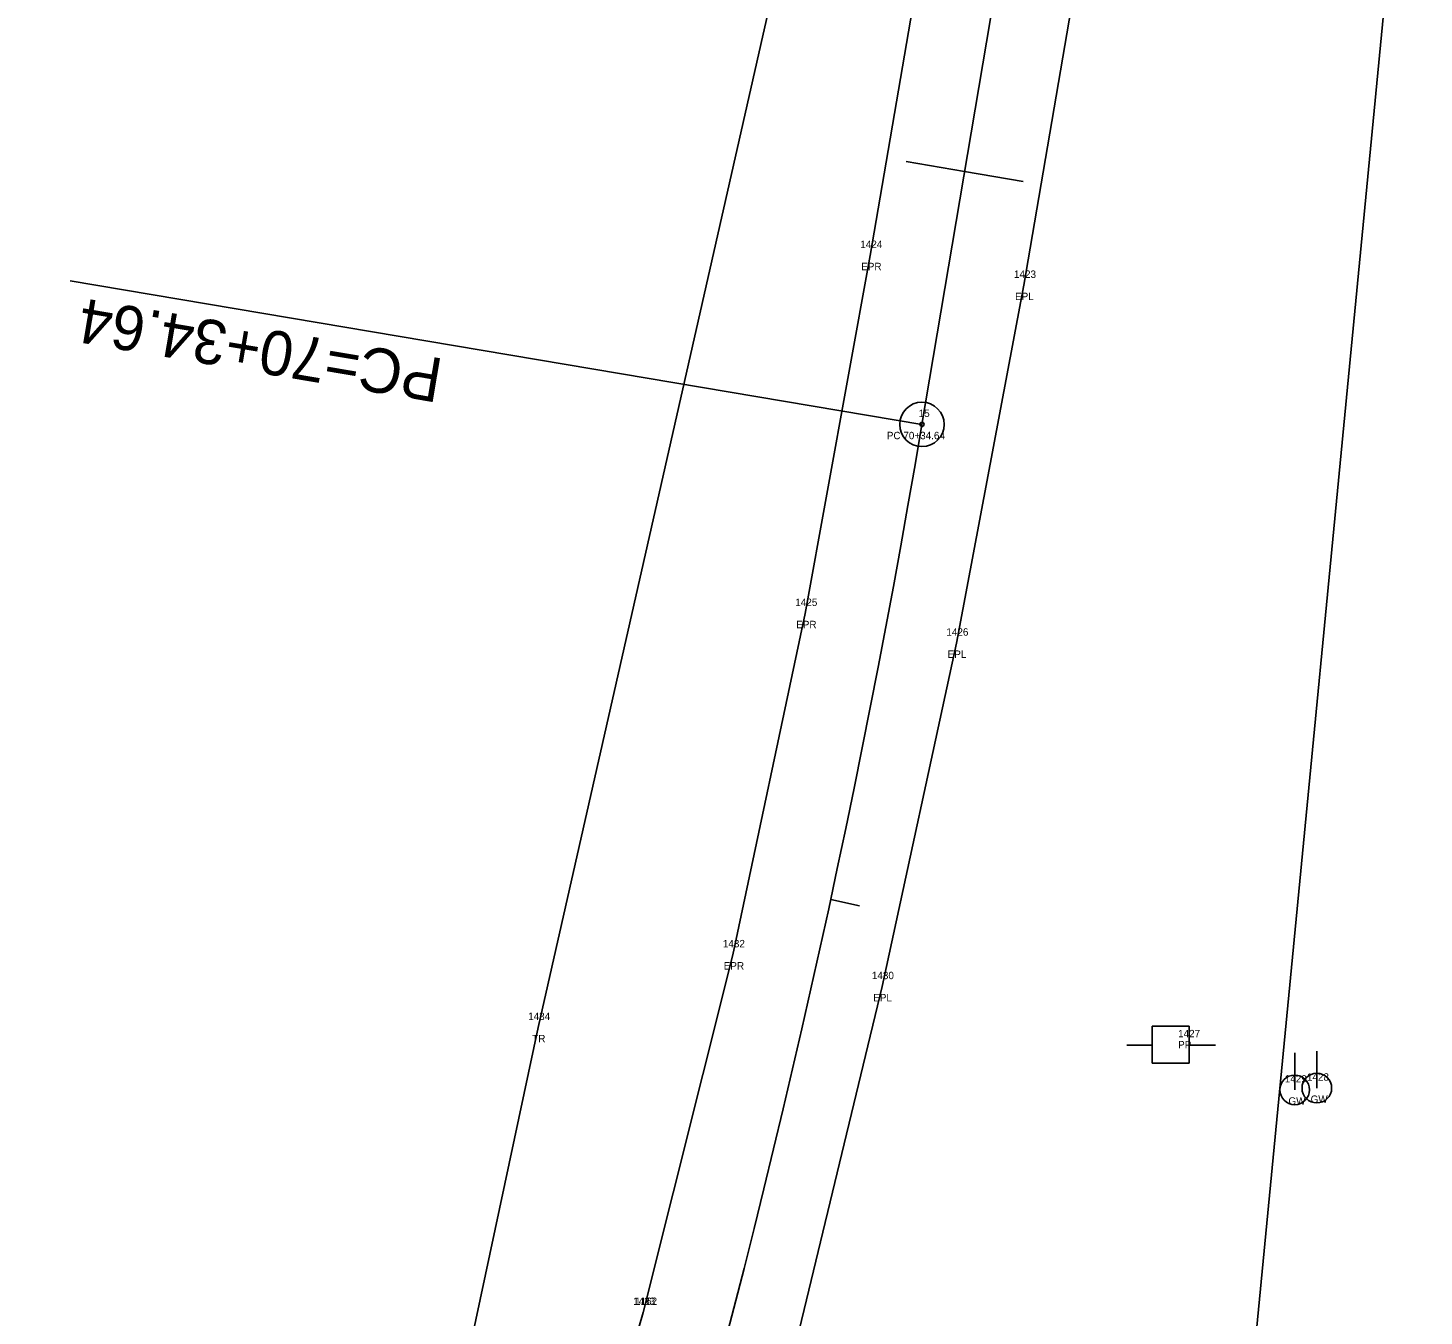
# Model space of a CAD drawing. Extents: x 2432632 to 2433497, y 684847 to 688233.
# Drawn here: x 2432974.5 to 2433163, y 685693.7 to 685867.7 of the extents above; entities that cross this region are included whole.
import ezdxf

# ---------------------------------------------------------------- set-up
doc = ezdxf.new("R2010")
doc.units = 0
for name, color, linetype in [('RD_EX_Road', 7, 'Continuous'), ('RD_EX_Road_txCode', 7, 'Continuous'), ('RD_EX_UT', 7, 'Continuous'), ('RD_EX_UT_txCode', 7, 'Continuous'), ('RD_EX_VEG', 7, 'Continuous'), ('RD_EX_VEG_txCode', 7, 'Continuous'), ('RD_HC_Cl', 7, 'Continuous'), ('RD_HC_Data', 7, 'Continuous'), ('RD_HC_Data_Tic', 7, 'Continuous'), ('RD_HC_txCode', 7, 'Continuous'), ('RD_SMD_Locator', 7, 'Continuous')]:
    doc.layers.add(name, color=color, linetype=linetype)

msp = doc.modelspace()

# ---------------------------------------------------------------- linework, layer by layer
at = {"layer": 'RD_EX_Road'}
for points in [[(2433117.43, 686021.83), (2433112.31, 685992.92), (2433104.52, 685948.7), (2433104.8, 685933.95), (2433088.22, 685836.98), (2433079.44, 685788.63), (2433069.66, 685742.53), (2433057.55, 685694.23)], [(2433142.75, 686017.3), (2433137.62, 685988.23), (2433129.83, 685944.15), (2433125.56, 685930.12), (2433108.96, 685832.94), (2433099.86, 685784.62), (2433089.82, 685738.23), (2433077.66, 685687.92)], [(2433057.55, 685694.23), (2433042.27, 685641.38), (2433024.96, 685589.31), (2433008.78, 685545.65), (2432989.83, 685496.35), (2432969.04, 685447.03), (2432957.98, 685420.84), (2432946.33, 685394.97), (2432928.47, 685353.31), (2432900.81, 685290.04), (2432890.58, 685267.74), (2432865.39, 685209.09), (2432858.68, 685194.25), (2432808.1, 685079.72), (2432767.11, 684987)]]:
    msp.add_lwpolyline(points, dxfattribs=at)
at = {"layer": 'RD_EX_UT'}
for p, q in [((2433131.28, 685732.89), (2433126.28, 685732.89)), ((2433126.28, 685732.89), (2433126.28, 685727.89)), ((2433131.28, 685727.89), (2433131.28, 685732.89)), ((2433122.84, 685730.33), (2433126.31, 685730.33)), ((2433131.2, 685730.33), (2433134.84, 685730.33)), ((2433145.52, 685724.28), (2433145.52, 685729.28)), ((2433148.51, 685724.52), (2433148.51, 685729.52)), ((2433126.28, 685727.89), (2433131.28, 685727.89))]:
    msp.add_line(p, q, dxfattribs=at)
for centre in [(2433145.52, 685724.28), (2433148.51, 685724.52)]:
    msp.add_circle(centre, 2, dxfattribs=at)
at = {"layer": 'RD_EX_VEG'}
msp.add_line((2433162.99, 685926.41), (2433137.8, 685665.13), dxfattribs=at)
msp.add_lwpolyline([(2433091.33, 685944.6), (2433043.36, 685732.71), (2433025.22, 685647.63)], dxfattribs=at)
at = {"layer": 'RD_HC_Cl'}
msp.add_line((2433147.9, 686126.86), (2433095.19, 685814.15), dxfattribs=at)
msp.add_arc((2431682.72, 686052.2), 1432.39, 336.23293, 350.43349, dxfattribs=at)
at = {"layer": 'RD_HC_Data'}
msp.add_line((2433095.19, 685814.15), (2432980.18, 685833.53), dxfattribs=at)
for radius in [3, 0.282]:
    msp.add_circle((2433095.19, 685814.15), radius, dxfattribs=at)
at = {"layer": 'RD_HC_Data_Tic'}
for p, q in [((2433100.95, 685848.31), (2433093.06, 685849.64)), ((2433100.95, 685848.31), (2433108.84, 685846.98)), ((2433082.87, 685749.97), (2433086.78, 685749.13))]:
    msp.add_line(p, q, dxfattribs=at)
at = {"layer": 'RD_SMD_Locator'}
for centre in [(2433088.22, 685836.98), (2433108.96, 685832.94), (2433095.19, 685814.15), (2433079.44, 685788.63), (2433099.86, 685784.62), (2433069.66, 685742.53), (2433089.82, 685738.23), (2433043.36, 685732.71), (2433057.55, 685694.23), (2433057.55, 685694.23)]:
    msp.add_circle(centre, 0.001, dxfattribs=at)

# ---------------------------------------------------------------- texts
at = {"layer": 'RD_EX_Road_txCode'}
for s, p in [('1424', (2433086.87, 685837.98)), ('EPR', (2433086.99, 685834.98)), ('1423', (2433107.62, 685833.94)), ('EPL', (2433107.76, 685830.94)), ('1425', (2433078.09, 685789.63)), ('EPR', (2433078.21, 685786.63)), ('1426', (2433098.49, 685785.62)), ('EPL', (2433098.66, 685782.62)), ('1432', (2433068.31, 685743.53)), ('EPR', (2433068.43, 685740.53)), ('1430', (2433088.43, 685739.23)), ('EPL', (2433088.61, 685736.23)), ('1433', (2433056.2, 685695.23)), ('1162', (2433056.46, 685695.23))]:
    msp.add_text(s, height=1, dxfattribs=at).set_placement(p)
at = {"layer": 'RD_EX_UT_txCode'}
for s, p in [('1427', (2433129.78, 685731.38)), ('PP', (2433129.78, 685729.88)), ('1429', (2433144.18, 685725.28)), ('1428', (2433147.17, 685725.52)), ('GW', (2433147.67, 685722.52)), ('GW', (2433144.68, 685722.28))]:
    msp.add_text(s, height=1, dxfattribs=at).set_placement(p)
at = {"layer": 'RD_EX_VEG_txCode'}
for s, p in [('1434', (2433042.02, 685733.71)), ('TR', (2433042.57, 685730.71))]:
    msp.add_text(s, height=1, dxfattribs=at).set_placement(p)
at = {"layer": 'RD_HC_Data'}
msp.add_text('PC=70+34.64', height=6, rotation=170.4335, dxfattribs=at).set_placement((2433030.77, 685822.98))
at = {"layer": 'RD_HC_txCode'}
for s, p in [('15', (2433094.75, 685815.15)), ('PC 70+34.64', (2433090.45, 685812.15))]:
    msp.add_text(s, height=1, dxfattribs=at).set_placement(p)

doc.saveas('drawing.dxf')
